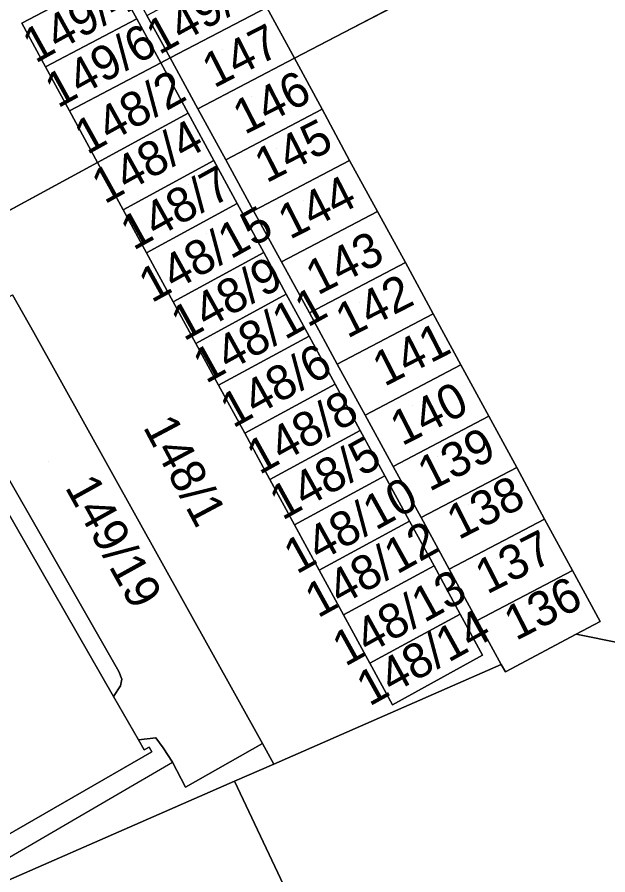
# Model space of a CAD drawing. Extents: x -264070 to -262271, y -1238894 to -1238141.
# Drawn here: x -263213.95 to -263179.93, y -1238690.43 to -1238641.04 of the extents above; entities that cross this region are included whole.
import ezdxf

# ---------------------------------------------------------------- set-up
doc = ezdxf.new("R2010")
doc.units = 0
for name, color, linetype in [('body_kn', 7, 'Continuous'), ('kladpar_druhypozemkov', 7, 'Continuous'), ('kladpar_hranice', 7, 'Continuous'), ('kladpar_parcelnecisla', 7, 'Continuous'), ('kladpar_plochy', 7, 'Continuous'), ('zappar_hrandruhpozemk', 7, 'Continuous')]:
    doc.layers.add(name, color=color, linetype=linetype)

msp = doc.modelspace()

# ---------------------------------------------------------------- linework, layer by layer
at = {"layer": 'body_kn'}
for p, q in [((-263213.68, -1238641.4), (-263213.68, -1238641.4)), ((-263207.05, -1238641.14), (-263207.05, -1238641.14)), ((-263207.05, -1238641.14), (-263207.05, -1238641.14)), ((-263205.14, -1238643.39), (-263205.14, -1238643.39)), ((-263197.98, -1238643.41), (-263197.98, -1238643.41)), ((-263197.98, -1238643.41), (-263197.98, -1238643.41)), ((-263212.31, -1238643.91), (-263212.31, -1238643.91)), ((-263205.68, -1238643.67), (-263205.68, -1238643.67)), ((-263205.68, -1238643.67), (-263205.68, -1238643.67)), ((-263203.54, -1238646.32), (-263203.54, -1238646.32)), ((-263196.39, -1238646.35), (-263196.39, -1238646.35)), ((-263196.39, -1238646.35), (-263196.39, -1238646.35)), ((-263210.94, -1238646.43), (-263210.94, -1238646.43)), ((-263204.1, -1238646.57), (-263204.1, -1238646.57)), ((-263204.1, -1238646.57), (-263204.1, -1238646.57)), ((-263202.63, -1238649.29), (-263202.63, -1238649.29)), ((-263202.63, -1238649.29), (-263202.63, -1238649.29)), ((-263201.94, -1238649.26), (-263201.94, -1238649.26)), ((-263194.8, -1238649.29), (-263194.8, -1238649.29)), ((-263194.8, -1238649.29), (-263194.8, -1238649.29)), ((-263209.32, -1238649.41), (-263209.32, -1238649.41)), ((-263201.28, -1238651.77), (-263201.28, -1238651.77)), ((-263201.28, -1238651.77), (-263201.28, -1238651.77)), ((-263207.84, -1238652.13), (-263207.84, -1238652.13)), ((-263200.34, -1238652.19), (-263200.34, -1238652.19)), ((-263193.19, -1238652.23), (-263193.19, -1238652.23)), ((-263193.19, -1238652.23), (-263193.19, -1238652.23)), ((-263206.5, -1238654.61), (-263206.5, -1238654.61)), ((-263199.75, -1238654.59), (-263199.75, -1238654.59)), ((-263199.75, -1238654.59), (-263199.75, -1238654.59)), ((-263198.72, -1238655.13), (-263198.72, -1238655.13)), ((-263191.59, -1238655.17), (-263191.59, -1238655.17)), ((-263191.59, -1238655.17), (-263191.59, -1238655.17)), ((-263198.45, -1238657), (-263198.45, -1238657)), ((-263198.45, -1238657), (-263198.45, -1238657)), ((-263204.96, -1238657.43), (-263204.96, -1238657.43)), ((-263204.96, -1238657.43), (-263204.96, -1238657.43)), ((-263197.12, -1238658.07), (-263197.12, -1238658.07)), ((-263189.99, -1238658.12), (-263189.99, -1238658.12)), ((-263189.99, -1238658.12), (-263189.99, -1238658.12)), ((-263212.99, -1238659.21), (-263212.99, -1238659.21)), ((-263197.14, -1238659.42), (-263197.14, -1238659.42)), ((-263197.14, -1238659.42), (-263197.14, -1238659.42)), ((-263203.66, -1238659.83), (-263203.66, -1238659.83)), ((-263195.51, -1238661.02), (-263195.51, -1238661.02)), ((-263188.39, -1238661.07), (-263188.39, -1238661.07)), ((-263188.39, -1238661.07), (-263188.39, -1238661.07)), ((-263195.64, -1238662.17), (-263195.64, -1238662.17)), ((-263195.64, -1238662.17), (-263195.64, -1238662.17)), ((-263202.35, -1238662.24), (-263202.35, -1238662.24)), ((-263193.91, -1238663.96), (-263193.91, -1238663.96)), ((-263186.79, -1238664.02), (-263186.79, -1238664.02)), ((-263186.79, -1238664.02), (-263186.79, -1238664.02)), ((-263200.84, -1238664.99), (-263200.84, -1238664.99)), ((-263194.19, -1238664.84), (-263194.19, -1238664.84)), ((-263194.19, -1238664.84), (-263194.19, -1238664.84)), ((-263192.3, -1238666.91), (-263192.3, -1238666.91)), ((-263185.18, -1238666.97), (-263185.18, -1238666.97)), ((-263185.18, -1238666.97), (-263185.18, -1238666.97)), ((-263192.77, -1238667.45), (-263192.77, -1238667.45)), ((-263192.77, -1238667.45), (-263192.77, -1238667.45)), ((-263199.39, -1238667.67), (-263199.39, -1238667.67)), ((-263191.35, -1238670.06), (-263191.35, -1238670.06)), ((-263191.35, -1238670.06), (-263191.35, -1238670.06)), ((-263190.69, -1238669.86), (-263190.69, -1238669.86)), ((-263183.57, -1238669.95), (-263183.57, -1238669.95)), ((-263183.57, -1238669.95), (-263183.57, -1238669.95)), ((-263197.97, -1238670.28), (-263197.97, -1238670.28)), ((-263196.56, -1238672.88), (-263196.56, -1238672.88)), ((-263189.94, -1238672.63), (-263189.94, -1238672.63)), ((-263189.94, -1238672.63), (-263189.94, -1238672.63)), ((-263189.07, -1238672.82), (-263189.07, -1238672.82)), ((-263181.96, -1238672.91), (-263181.96, -1238672.91)), ((-263181.96, -1238672.91), (-263181.96, -1238672.91)), ((-263195.15, -1238675.46), (-263195.15, -1238675.46)), ((-263188.43, -1238675.42), (-263188.43, -1238675.42)), ((-263188.43, -1238675.42), (-263188.43, -1238675.42)), ((-263187.46, -1238675.78), (-263187.46, -1238675.78)), ((-263180.37, -1238675.85), (-263180.37, -1238675.85)), ((-263181.76, -1238676.58), (-263181.76, -1238676.58)), ((-263187.15, -1238677.78), (-263187.15, -1238677.78)), ((-263193.64, -1238678.25), (-263193.64, -1238678.25)), ((-263186.07, -1238678.32), (-263186.07, -1238678.32)), ((-263208.1, -1238678.73), (-263208.1, -1238678.73)), ((-263185.83, -1238678.74), (-263185.83, -1238678.74)), ((-263207.92, -1238679.17), (-263207.92, -1238679.17)), ((-263208, -1238679.55), (-263208, -1238679.55)), ((-263208.4, -1238680.17), (-263208.4, -1238680.17)), ((-263192.34, -1238680.65), (-263192.34, -1238680.65)), ((-263206.97, -1238682.66), (-263206.97, -1238682.66)), ((-263205.96, -1238682.54), (-263205.96, -1238682.54)), ((-263199.82, -1238682.86), (-263199.82, -1238682.86)), ((-263206.64, -1238683.24), (-263206.64, -1238683.24)), ((-263206.35, -1238683.08), (-263206.35, -1238683.08)), ((-263206.19, -1238683.34), (-263206.19, -1238683.34)), ((-263205.54, -1238683.12), (-263205.54, -1238683.12)), ((-263205, -1238683.95), (-263205, -1238683.95)), ((-263199.16, -1238684.05), (-263199.16, -1238684.05)), ((-263204.26, -1238685.39), (-263204.26, -1238685.39)), ((-263201.43, -1238685.04), (-263201.43, -1238685.04))]:
    msp.add_line(p, q, dxfattribs=at)
at = {"layer": 'kladpar_druhypozemkov'}
for p, q in [((-263208.92, -1238642.82), (-263208.92, -1238642.82)), ((-263202.11, -1238642.92), (-263202.11, -1238642.92)), ((-263206.91, -1238645.23), (-263206.91, -1238645.23)), ((-263200.47, -1238645.63), (-263200.47, -1238645.63)), ((-263205.45, -1238648.02), (-263205.45, -1238648.02)), ((-263199, -1238648.63), (-263199, -1238648.63)), ((-263204.07, -1238650.66), (-263204.07, -1238650.66)), ((-263197.47, -1238651.62), (-263197.47, -1238651.62)), ((-263203.02, -1238653.48), (-263203.02, -1238653.48)), ((-263195.89, -1238654.79), (-263195.89, -1238654.79)), ((-263201.22, -1238656.07), (-263201.22, -1238656.07)), ((-263194.25, -1238657.5), (-263194.25, -1238657.5)), ((-263200.03, -1238658.55), (-263200.03, -1238658.55)), ((-263192.56, -1238660.49), (-263192.56, -1238660.49)), ((-263198.49, -1238660.89), (-263198.49, -1238660.89)), ((-263197.1, -1238663.67), (-263197.1, -1238663.67)), ((-263191.2, -1238663.43), (-263191.2, -1238663.43)), ((-263212.14, -1238666.62), (-263212.14, -1238666.62)), ((-263203.5, -1238666.47), (-263203.5, -1238666.47)), ((-263195.72, -1238666.33), (-263195.72, -1238666.33)), ((-263189.73, -1238666.37), (-263189.73, -1238666.37)), ((-263194.67, -1238669.04), (-263194.67, -1238669.04)), ((-263187.98, -1238669.08), (-263187.98, -1238669.08)), ((-263193.26, -1238671.65), (-263193.26, -1238671.65)), ((-263186.34, -1238672.24), (-263186.34, -1238672.24)), ((-263191.87, -1238674.31), (-263191.87, -1238674.31)), ((-263184.59, -1238674.96), (-263184.59, -1238674.96)), ((-263190.22, -1238677.01), (-263190.22, -1238677.01))]:
    msp.add_line(p, q, dxfattribs=at)
at = {"layer": 'kladpar_hranice'}
for points in [[(-263170.34, -1238624.54), (-263183.61, -1238631.76), (-263181.86, -1238635), (-263197.98, -1238643.41), (-263199.57, -1238640.48), (-263200.92, -1238637.98), (-263202.43, -1238635.22), (-263207.92, -1238638.32), (-263206.48, -1238640.95), (-263205.14, -1238643.39), (-263205.68, -1238643.67), (-263207.05, -1238641.14), (-263208.43, -1238638.62), (-263213.68, -1238641.4), (-263212.31, -1238643.91), (-263210.94, -1238646.43), (-263209.32, -1238649.41), (-263216.36, -1238653.24), (-263233.66, -1238662.65), (-263237.17, -1238653.7), (-263241.51, -1238642.66)], [(-263160.98, -1238697.36), (-263177.21, -1238681.35), (-263179.18, -1238677.09), (-263181.76, -1238676.58), (-263180.37, -1238675.85), (-263181.96, -1238672.91), (-263183.57, -1238669.95), (-263185.18, -1238666.97), (-263186.79, -1238664.02), (-263188.39, -1238661.07), (-263189.99, -1238658.12), (-263191.59, -1238655.17), (-263193.19, -1238652.23), (-263194.8, -1238649.29), (-263196.39, -1238646.35), (-263197.98, -1238643.41), (-263181.86, -1238635)], [(-263200.92, -1238637.98), (-263199.57, -1238640.48), (-263205.14, -1238643.39), (-263206.48, -1238640.95), (-263200.92, -1238637.98)], [(-263208.43, -1238638.62), (-263207.05, -1238641.14), (-263212.31, -1238643.91), (-263213.68, -1238641.4), (-263208.43, -1238638.62)], [(-263199.57, -1238640.48), (-263197.98, -1238643.41), (-263203.54, -1238646.32), (-263205.14, -1238643.39), (-263199.57, -1238640.48)], [(-263207.05, -1238641.14), (-263205.68, -1238643.67), (-263210.94, -1238646.43), (-263212.31, -1238643.91), (-263207.05, -1238641.14)], [(-263204.96, -1238657.43), (-263203.66, -1238659.83), (-263202.35, -1238662.24), (-263200.84, -1238664.99), (-263199.39, -1238667.67), (-263197.97, -1238670.28), (-263196.56, -1238672.88), (-263195.15, -1238675.46), (-263193.64, -1238678.25), (-263192.34, -1238680.65), (-263187.15, -1238677.78), (-263188.43, -1238675.42), (-263189.94, -1238672.63), (-263191.35, -1238670.06), (-263192.77, -1238667.45), (-263194.19, -1238664.84), (-263195.64, -1238662.17), (-263197.14, -1238659.42), (-263198.45, -1238657), (-263199.75, -1238654.59), (-263201.28, -1238651.77), (-263202.63, -1238649.29), (-263204.1, -1238646.57), (-263205.68, -1238643.67), (-263205.14, -1238643.39), (-263203.54, -1238646.32), (-263201.94, -1238649.26), (-263200.34, -1238652.19), (-263198.72, -1238655.13), (-263197.12, -1238658.07), (-263195.51, -1238661.02), (-263193.91, -1238663.96), (-263192.3, -1238666.91), (-263190.69, -1238669.86), (-263189.07, -1238672.82), (-263187.46, -1238675.78), (-263186.07, -1238678.32), (-263199.16, -1238684.05), (-263199.82, -1238682.86), (-263212.99, -1238659.21), (-263214.22, -1238657.04)], [(-263197.98, -1238643.41), (-263196.39, -1238646.35), (-263201.94, -1238649.26), (-263203.54, -1238646.32), (-263197.98, -1238643.41)], [(-263205.68, -1238643.67), (-263204.1, -1238646.57), (-263209.32, -1238649.41), (-263210.94, -1238646.43), (-263205.68, -1238643.67)], [(-263196.39, -1238646.35), (-263194.8, -1238649.29), (-263200.34, -1238652.19), (-263201.94, -1238649.26), (-263196.39, -1238646.35)], [(-263204.1, -1238646.57), (-263202.63, -1238649.29), (-263207.84, -1238652.13), (-263209.32, -1238649.41), (-263204.1, -1238646.57)], [(-263202.63, -1238649.29), (-263201.28, -1238651.77), (-263206.5, -1238654.61), (-263207.84, -1238652.13), (-263202.63, -1238649.29)], [(-263194.8, -1238649.29), (-263193.19, -1238652.23), (-263198.72, -1238655.13), (-263200.34, -1238652.19), (-263194.8, -1238649.29)], [(-263216.36, -1238653.24), (-263209.32, -1238649.41), (-263207.84, -1238652.13), (-263206.5, -1238654.61), (-263204.96, -1238657.43)], [(-263201.28, -1238651.77), (-263199.75, -1238654.59), (-263204.96, -1238657.43), (-263206.5, -1238654.61), (-263201.28, -1238651.77)], [(-263193.19, -1238652.23), (-263191.59, -1238655.17), (-263197.12, -1238658.07), (-263198.72, -1238655.13), (-263193.19, -1238652.23)], [(-263199.75, -1238654.59), (-263198.45, -1238657), (-263203.66, -1238659.83), (-263204.96, -1238657.43), (-263199.75, -1238654.59)], [(-263191.59, -1238655.17), (-263189.99, -1238658.12), (-263195.51, -1238661.02), (-263197.12, -1238658.07), (-263191.59, -1238655.17)], [(-263219, -1238659.69), (-263214.22, -1238657.04), (-263212.99, -1238659.21), (-263199.82, -1238682.86), (-263204.26, -1238685.39), (-263205, -1238683.95), (-263205.54, -1238683.12), (-263205.96, -1238682.54), (-263206.97, -1238682.66), (-263208.4, -1238680.17), (-263208, -1238679.55), (-263207.92, -1238679.17), (-263208.1, -1238678.73), (-263219, -1238659.69)], [(-263198.45, -1238657), (-263197.14, -1238659.42), (-263202.35, -1238662.24), (-263203.66, -1238659.83), (-263198.45, -1238657)], [(-263231.54, -1238664), (-263220.85, -1238657.86), (-263220.7, -1238658.12), (-263220.98, -1238658.28), (-263208.4, -1238680.17), (-263206.97, -1238682.66), (-263206.64, -1238683.24), (-263206.35, -1238683.08), (-263206.19, -1238683.34), (-263216.9, -1238689.5), (-263217.05, -1238689.23), (-263216.76, -1238689.06), (-263220.26, -1238682.97), (-263231.1, -1238664.11), (-263231.38, -1238664.27), (-263231.54, -1238664)], [(-263189.99, -1238658.12), (-263188.39, -1238661.07), (-263193.91, -1238663.96), (-263195.51, -1238661.02), (-263189.99, -1238658.12)], [(-263219, -1238659.69), (-263208.1, -1238678.73), (-263207.92, -1238679.17), (-263208, -1238679.55), (-263208.4, -1238680.17), (-263220.98, -1238658.28)], [(-263197.14, -1238659.42), (-263195.64, -1238662.17), (-263200.84, -1238664.99), (-263202.35, -1238662.24), (-263197.14, -1238659.42)], [(-263188.39, -1238661.07), (-263186.79, -1238664.02), (-263192.3, -1238666.91), (-263193.91, -1238663.96), (-263188.39, -1238661.07)], [(-263195.64, -1238662.17), (-263194.19, -1238664.84), (-263199.39, -1238667.67), (-263200.84, -1238664.99), (-263195.64, -1238662.17)], [(-263186.79, -1238664.02), (-263185.18, -1238666.97), (-263190.69, -1238669.86), (-263192.3, -1238666.91), (-263186.79, -1238664.02)], [(-263194.19, -1238664.84), (-263192.77, -1238667.45), (-263197.97, -1238670.28), (-263199.39, -1238667.67), (-263194.19, -1238664.84)], [(-263185.18, -1238666.97), (-263183.57, -1238669.95), (-263189.07, -1238672.82), (-263190.69, -1238669.86), (-263185.18, -1238666.97)], [(-263192.77, -1238667.45), (-263191.35, -1238670.06), (-263196.56, -1238672.88), (-263197.97, -1238670.28), (-263192.77, -1238667.45)], [(-263191.35, -1238670.06), (-263189.94, -1238672.63), (-263195.15, -1238675.46), (-263196.56, -1238672.88), (-263191.35, -1238670.06)], [(-263183.57, -1238669.95), (-263181.96, -1238672.91), (-263187.46, -1238675.78), (-263189.07, -1238672.82), (-263183.57, -1238669.95)], [(-263189.94, -1238672.63), (-263188.43, -1238675.42), (-263193.64, -1238678.25), (-263195.15, -1238675.46), (-263189.94, -1238672.63)], [(-263181.96, -1238672.91), (-263180.37, -1238675.85), (-263181.76, -1238676.58), (-263185.83, -1238678.74), (-263186.07, -1238678.32), (-263187.46, -1238675.78), (-263181.96, -1238672.91)], [(-263188.43, -1238675.42), (-263187.15, -1238677.78), (-263192.34, -1238680.65), (-263193.64, -1238678.25), (-263188.43, -1238675.42)], [(-263179.18, -1238677.09), (-263177.21, -1238681.35), (-263160.98, -1238697.36), (-263160.14, -1238698.47), (-263162.57, -1238701.25), (-263163.08, -1238699.74), (-263177.03, -1238705.67), (-263174, -1238712.8), (-263186.02, -1238717.64), (-263201.43, -1238685.04), (-263199.16, -1238684.05), (-263186.07, -1238678.32), (-263185.83, -1238678.74), (-263181.76, -1238676.58), (-263179.18, -1238677.09)], [(-263216.9, -1238689.5), (-263206.19, -1238683.34), (-263206.35, -1238683.08), (-263206.64, -1238683.24), (-263206.97, -1238682.66), (-263205.96, -1238682.54), (-263205.54, -1238683.12), (-263205, -1238683.95), (-263204.26, -1238685.39), (-263199.82, -1238682.86), (-263199.16, -1238684.05), (-263201.43, -1238685.04), (-263220.21, -1238693.26)], [(-263220.21, -1238693.26), (-263201.43, -1238685.04), (-263186.02, -1238717.64)]]:
    msp.add_lwpolyline(points, dxfattribs=at)
at = {"layer": 'kladpar_plochy'}
for p, q in [((-263181.86, -1238635), (-263197.98, -1238643.41)), ((-263197.98, -1238643.41), (-263181.86, -1238635)), ((-263208.43, -1238638.62), (-263213.68, -1238641.4)), ((-263207.05, -1238641.14), (-263208.43, -1238638.62)), ((-263197.98, -1238643.41), (-263199.57, -1238640.48)), ((-263206.48, -1238640.95), (-263205.14, -1238643.39)), ((-263213.68, -1238641.4), (-263212.31, -1238643.91)), ((-263205.68, -1238643.67), (-263207.05, -1238641.14)), ((-263205.14, -1238643.39), (-263205.68, -1238643.67)), ((-263196.39, -1238646.35), (-263197.98, -1238643.41)), ((-263212.31, -1238643.91), (-263210.94, -1238646.43)), ((-263194.8, -1238649.29), (-263196.39, -1238646.35)), ((-263210.94, -1238646.43), (-263209.32, -1238649.41)), ((-263193.19, -1238652.23), (-263194.8, -1238649.29)), ((-263209.32, -1238649.41), (-263216.36, -1238653.24)), ((-263191.59, -1238655.17), (-263193.19, -1238652.23)), ((-263189.99, -1238658.12), (-263191.59, -1238655.17)), ((-263188.39, -1238661.07), (-263189.99, -1238658.12)), ((-263186.79, -1238664.02), (-263188.39, -1238661.07)), ((-263185.18, -1238666.97), (-263186.79, -1238664.02)), ((-263183.57, -1238669.95), (-263185.18, -1238666.97)), ((-263181.96, -1238672.91), (-263183.57, -1238669.95)), ((-263180.37, -1238675.85), (-263181.96, -1238672.91)), ((-263181.76, -1238676.58), (-263180.37, -1238675.85)), ((-263179.18, -1238677.09), (-263181.76, -1238676.58))]:
    msp.add_line(p, q, dxfattribs=at)
for points in [[(-263200.92, -1238637.98), (-263199.57, -1238640.48), (-263205.14, -1238643.39), (-263206.48, -1238640.95)], [(-263208.43, -1238638.62), (-263207.05, -1238641.14), (-263212.31, -1238643.91), (-263213.68, -1238641.4)], [(-263199.57, -1238640.48), (-263197.98, -1238643.41), (-263203.54, -1238646.32), (-263205.14, -1238643.39)], [(-263207.05, -1238641.14), (-263205.68, -1238643.67), (-263210.94, -1238646.43), (-263212.31, -1238643.91)], [(-263197.98, -1238643.41), (-263196.39, -1238646.35), (-263201.94, -1238649.26), (-263203.54, -1238646.32)], [(-263205.68, -1238643.67), (-263204.1, -1238646.57), (-263209.32, -1238649.41), (-263210.94, -1238646.43)], [(-263196.39, -1238646.35), (-263194.8, -1238649.29), (-263200.34, -1238652.19), (-263201.94, -1238649.26)], [(-263204.1, -1238646.57), (-263202.63, -1238649.29), (-263207.84, -1238652.13), (-263209.32, -1238649.41)], [(-263202.63, -1238649.29), (-263201.28, -1238651.77), (-263206.5, -1238654.61), (-263207.84, -1238652.13)], [(-263194.8, -1238649.29), (-263193.19, -1238652.23), (-263198.72, -1238655.13), (-263200.34, -1238652.19)], [(-263201.28, -1238651.77), (-263199.75, -1238654.59), (-263204.96, -1238657.43), (-263206.5, -1238654.61)], [(-263193.19, -1238652.23), (-263191.59, -1238655.17), (-263197.12, -1238658.07), (-263198.72, -1238655.13)], [(-263199.75, -1238654.59), (-263198.45, -1238657), (-263203.66, -1238659.83), (-263204.96, -1238657.43)], [(-263191.59, -1238655.17), (-263189.99, -1238658.12), (-263195.51, -1238661.02), (-263197.12, -1238658.07)], [(-263219, -1238659.69), (-263214.22, -1238657.04), (-263212.99, -1238659.21), (-263199.82, -1238682.86), (-263204.26, -1238685.39), (-263205, -1238683.95), (-263205.54, -1238683.12), (-263205.96, -1238682.54), (-263206.97, -1238682.66), (-263208.4, -1238680.17), (-263208, -1238679.55), (-263207.92, -1238679.17), (-263208.1, -1238678.73)], [(-263198.45, -1238657), (-263197.14, -1238659.42), (-263202.35, -1238662.24), (-263203.66, -1238659.83)], [(-263231.54, -1238664), (-263220.85, -1238657.86), (-263220.7, -1238658.12), (-263220.98, -1238658.28), (-263208.4, -1238680.17), (-263206.97, -1238682.66), (-263206.64, -1238683.24), (-263206.35, -1238683.08), (-263206.19, -1238683.34), (-263216.9, -1238689.5), (-263217.05, -1238689.23), (-263216.76, -1238689.06), (-263220.26, -1238682.97), (-263231.1, -1238664.11), (-263231.38, -1238664.27)], [(-263189.99, -1238658.12), (-263188.39, -1238661.07), (-263193.91, -1238663.96), (-263195.51, -1238661.02)], [(-263197.14, -1238659.42), (-263195.64, -1238662.17), (-263200.84, -1238664.99), (-263202.35, -1238662.24)], [(-263188.39, -1238661.07), (-263186.79, -1238664.02), (-263192.3, -1238666.91), (-263193.91, -1238663.96)], [(-263195.64, -1238662.17), (-263194.19, -1238664.84), (-263199.39, -1238667.67), (-263200.84, -1238664.99)], [(-263186.79, -1238664.02), (-263185.18, -1238666.97), (-263190.69, -1238669.86), (-263192.3, -1238666.91)], [(-263194.19, -1238664.84), (-263192.77, -1238667.45), (-263197.97, -1238670.28), (-263199.39, -1238667.67)], [(-263185.18, -1238666.97), (-263183.57, -1238669.95), (-263189.07, -1238672.82), (-263190.69, -1238669.86)], [(-263192.77, -1238667.45), (-263191.35, -1238670.06), (-263196.56, -1238672.88), (-263197.97, -1238670.28)], [(-263191.35, -1238670.06), (-263189.94, -1238672.63), (-263195.15, -1238675.46), (-263196.56, -1238672.88)], [(-263183.57, -1238669.95), (-263181.96, -1238672.91), (-263187.46, -1238675.78), (-263189.07, -1238672.82)], [(-263189.94, -1238672.63), (-263188.43, -1238675.42), (-263193.64, -1238678.25), (-263195.15, -1238675.46)], [(-263181.96, -1238672.91), (-263180.37, -1238675.85), (-263181.76, -1238676.58), (-263185.83, -1238678.74), (-263186.07, -1238678.32), (-263187.46, -1238675.78)], [(-263188.43, -1238675.42), (-263187.15, -1238677.78), (-263192.34, -1238680.65), (-263193.64, -1238678.25)], [(-263179.18, -1238677.09), (-263177.21, -1238681.35), (-263160.98, -1238697.36), (-263160.14, -1238698.47), (-263162.57, -1238701.25), (-263163.08, -1238699.74), (-263177.03, -1238705.67), (-263174, -1238712.8), (-263186.02, -1238717.64), (-263201.43, -1238685.04), (-263199.16, -1238684.05), (-263186.07, -1238678.32), (-263185.83, -1238678.74), (-263181.76, -1238676.58)]]:
    msp.add_lwpolyline(points, close=True, dxfattribs=at)
for points in [[(-263216.36, -1238653.24), (-263209.32, -1238649.41), (-263207.84, -1238652.13), (-263206.5, -1238654.61), (-263204.96, -1238657.43), (-263203.66, -1238659.83), (-263202.35, -1238662.24), (-263200.84, -1238664.99), (-263199.39, -1238667.67), (-263197.97, -1238670.28), (-263196.56, -1238672.88), (-263195.15, -1238675.46), (-263193.64, -1238678.25), (-263192.34, -1238680.65), (-263187.15, -1238677.78), (-263188.43, -1238675.42), (-263189.94, -1238672.63), (-263191.35, -1238670.06), (-263192.77, -1238667.45), (-263194.19, -1238664.84), (-263195.64, -1238662.17), (-263197.14, -1238659.42), (-263198.45, -1238657), (-263199.75, -1238654.59), (-263201.28, -1238651.77), (-263202.63, -1238649.29), (-263204.1, -1238646.57), (-263205.68, -1238643.67), (-263205.14, -1238643.39), (-263203.54, -1238646.32), (-263201.94, -1238649.26), (-263200.34, -1238652.19), (-263198.72, -1238655.13), (-263197.12, -1238658.07), (-263195.51, -1238661.02), (-263193.91, -1238663.96), (-263192.3, -1238666.91), (-263190.69, -1238669.86), (-263189.07, -1238672.82), (-263187.46, -1238675.78), (-263186.07, -1238678.32), (-263199.16, -1238684.05), (-263199.82, -1238682.86), (-263212.99, -1238659.21), (-263214.22, -1238657.04)], [(-263219, -1238659.69), (-263208.1, -1238678.73), (-263207.92, -1238679.17), (-263208, -1238679.55), (-263208.4, -1238680.17), (-263220.98, -1238658.28)], [(-263216.9, -1238689.5), (-263206.19, -1238683.34), (-263206.35, -1238683.08), (-263206.64, -1238683.24), (-263206.97, -1238682.66), (-263205.96, -1238682.54), (-263205.54, -1238683.12), (-263205, -1238683.95), (-263204.26, -1238685.39), (-263199.82, -1238682.86), (-263199.16, -1238684.05), (-263201.43, -1238685.04), (-263220.21, -1238693.26)], [(-263220.21, -1238693.26), (-263201.43, -1238685.04), (-263186.02, -1238717.64)]]:
    msp.add_lwpolyline(points, dxfattribs=at)
at = {"layer": 'zappar_hrandruhpozemk'}
msp.add_line((-263217.44, -1238691.19), (-263205, -1238683.95), dxfattribs=at)

# ---------------------------------------------------------------- texts
at = {"layer": 'kladpar_parcelnecisla'}
for s, rotation, p in [('149/5', 29, (-263205.778, -1238643.241)), ('149/4', 29, (-263212.9, -1238643.734)), ('149/6', 29, (-263211.61, -1238646.314)), ('147', 27, (-263202.617, -1238645.157)), ('148/2', 29, (-263209.923, -1238648.992)), ('146', 27, (-263200.85, -1238647.839)), ('148/4', 29, (-263208.917, -1238651.84)), ('145', 27, (-263199.599, -1238650.624)), ('148/7', 29, (-263207.256, -1238654.507)), ('144', 27, (-263198.25, -1238653.879)), ('148/15', 29, (-263206.207, -1238657.531)), ('143', 27, (-263196.651, -1238657.085)), ('148/9', 29, (-263204.347, -1238659.73)), ('142', 27, (-263194.937, -1238659.568)), ('148/11', 29, (-263203.08, -1238662.176)), ('141', 27, (-263192.805, -1238662.343)), ('148/6', 29, (-263201.517, -1238664.74)), ('140', 27, (-263191.788, -1238665.763)), ('148/8', 29, (-263199.998, -1238667.421)), ('148/1', 298, (-263206.729, -1238664.638)), ('148/5', 29, (-263198.675, -1238670.046)), ('139', 27, (-263190.211, -1238668.385)), ('149/19', 299, (-263211.229, -1238668.109)), ('148/10', 29, (-263197.856, -1238673.149)), ('138', 27, (-263188.532, -1238671.166)), ('148/12', 29, (-263196.634, -1238675.676)), ('137', 27, (-263186.889, -1238674.304)), ('148/13', 29, (-263195.058, -1238678.464)), ('136', 27, (-263185.231, -1238676.975)), ('148/14', 29, (-263193.668, -1238680.754))]:
    msp.add_text(s, height=2, rotation=rotation, dxfattribs=at).set_placement(p)

doc.saveas('drawing.dxf')
